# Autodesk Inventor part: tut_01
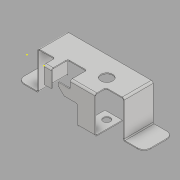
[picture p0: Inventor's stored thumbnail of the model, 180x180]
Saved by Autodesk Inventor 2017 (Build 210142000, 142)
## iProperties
Created: 2015-06
Part Number: tut_01
Material: Generic
Document SubType Name: Sheet Metal
Designer: Sandeep
Density: 1 g/cm^3
Sheet Metal Rule: Default_mm
Appearance: Default
Author: Sandeep
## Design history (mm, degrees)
node "Face1"
  sketch "Sketch1"
    geometry: L1 (0, 12)-(0, 44); L2 (0, 44)-(95, 44); L3 (95, 44)-(95, 12); L4 (95, 12)-(75, 12); L5 (75, 12)-(75, 0); L6 (75, 0)-(48, 0); L7 (48, 0)-(48, 18); L8 (48, 18)-(27, 18); L9 (27, 18)-(27, 0); L10 (27, 0)-(19, 0); L11 (19, 0)-(19, 12); L12 (19, 12)-(0, 12); L13 (0, 0)-(0, 88.508); L14 (0, 0)-(152.255, 0)
    constraints: 28 end point, 11 perpendicular, 4 point on line, 2 vertical, 1 horizontal
    dimensions: "d0" = 26 distance between parallel lines of L2 L8; "d1" = 19 distance between parallel lines of L13 L11; "d2" = 8 distance between parallel lines of L9 L11; "d3" = 32 distance between parallel lines of L12 L2; "d4" = 27 distance between parallel lines of L5 L7; "d5" = 20 distance between parallel lines of L3 L5; "d6" = 95 distance between parallel lines of L1 L3; "d7" = 44 distance between parallel lines of L6 L2
node "Contour Flange1"
sketch "Sketch7"
  geometry: 1 further point
node "Contour Flange3"
  sketch "Sketch10"
    geometry: L1 (0, 0)-(41, 0); L2 (41, 0)-(41, 30)
    constraints: 4 end point, 1 horizontal, 1 perpendicular
    dimensions: "d42" = 41 distance of L1.start L1.end; "d43" = 30 distance of L1.end L2.end
sketch "Sketch11"
  geometry: L1 (-3.447, 20)-(8, 20); L2 (8, 20)-(8, -8.777); L3 (8, -8.777)-(-3.447, -8.777); L4 (-3.447, -8.777)-(-3.447, 20); L5 (-21, 39)-(0, 39) reference; L6 (27, 37)-(27, 0) reference; 1 further point
  constraints: 8 end point, 2 parallel, 1 horizontal, 1 perpendicular
  dimensions: "d44" = 19 distance between parallel lines of L1 L5; "d45" = 19 distance between parallel lines of L6 L2
cut "Cut1" sketch "Sketch11" dims "d46" = 1 (= Thickness), "d47" = 0
node "Face2"
  sketch "Sketch12"
    geometry: L1 (0, -17)-(-13, -17); L2 (-13, -17)-(-13, -7); L3 (-13, -7)-(0, -7); L4 (0, 0)-(0, -17) reference; 1 further point
    constraints: 6 end point, 2 perpendicular, 1 horizontal, 1 point on line
    dimensions: "d54" = 13 distance between parallel lines of L2 L4; "d55" = 10 distance of L1.end L2.end
feature "Corner Round1" dims "d56" = 2
feature "Corner Chamfer1" dims "d57" = 6, "d58" = 6, angle "d59" = 45 deg
node "Flange1"
sketch "Sketch14"
  geometry: 1 further point
hole "Hole1" diameter "d72" = 13; stored, may be unused: countersink angle "d76" = 90 deg, drill point angle "d78" = 0 deg; dims "d70" = 9, "d71" = 22, "d73" = 6, "d74" = 4, "d75" = 2, "d77" = 1 (= Thickness)
hole "Hole2" diameter "d81" = 8; stored, may be unused: countersink angle "d85" = 90 deg, drill point angle "d87" = 0 deg; dims "d79" = 9, "d80" = 22, "d82" = 6, "d83" = 4, "d84" = 2, "d86" = 1 (= Thickness)
feature "Corner Round2" dims "d88" = 7
feature "Corner Round3" dims "d89" = 2
workplane "Work Plane1"
node "Contour Flange4"
  sketch "Sketch15"
    geometry: L1 (0, 0.919)-(0, -40.081); L2 (0, -40.081)-(-22, -40.081); 1 further point
    constraints: 4 end point, 1 perpendicular, 1 vertical
    dimensions: "d90" = 41 distance of L1.start L1.end; "d91" = 22 distance of L1.end L2.end
feature "Corner Round4" dims "d101" = 7
feature "Corner Round5" dims "d102" = 2
body "Solid1"
face "Plate1" dims "Thickness" = 1 (derived)
sketch "Sketch6"
  geometry: L1 (-75, 1)-(20, 1) reference; L2 (20, 1)-(20, -39); L3 (20, -39)-(42, -39); L4 (-75, 1)-(-75, -39); L5 (-75, -39)-(-97, -39); 1 further point
  constraints: 8 end point, 2 perpendicular, 2 vertical
  dimensions: "d9" = 40 distance of L1.end L2.end; "d10" = 22 distance of L2.end L3.end; "d20" = 40 distance of L1.start L4.end
face "Plate2" dims "d11" = 1 (= BendReliefWidth), "d12" = 0.5 (= BendReliefDepth), "d13" = 2 (= MinimumRemnant), "d14" = 1 (= BendRadius), "d15" = 1 (= BendRadius), "d16" = 1, "d17" = 4 (= CornerReliefSize), "d18" = 1 (= GapSize), "d19" = 1 (= JacobiRadiusSize), "SeamGap" = 0.01, "Thickness" = 1 (derived)
bend "Bend1" dims "d11" = 1 (= BendReliefWidth), "d12" = 0.5 (= BendReliefDepth), "d13" = 2 (= MinimumRemnant), "d14" = 1 (= BendRadius), "d15" = 1 (= BendRadius), "d16" = 1, "SeamGap" = 0.01, "Thickness" = 1 (derived)
feature "Corner1" dims "d16" = 1, "d17" = 4 (= CornerReliefSize), "d18" = 1 (= GapSize), "d19" = 1 (= JacobiRadiusSize)
face "Plate4" dims "d33" = 1 (= BendReliefWidth), "d34" = 0.5 (= BendReliefDepth), "d35" = 2 (= MinimumRemnant), "d36" = 1 (= BendRadius), "d37" = 1 (= BendRadius), "d38" = 1, "d39" = 4 (= CornerReliefSize), "d40" = 1 (= GapSize), "d41" = 1 (= JacobiRadiusSize), "SeamGap" = 0.01, "Thickness" = 1 (derived)
bend "Bend3" dims "d33" = 1 (= BendReliefWidth), "d34" = 0.5 (= BendReliefDepth), "d35" = 2 (= MinimumRemnant), "d36" = 1 (= BendRadius), "d37" = 1 (= BendRadius), "d38" = 1, "SeamGap" = 0.01, "Thickness" = 1 (derived)
feature "Corner3" dims "d38" = 1, "d39" = 4 (= CornerReliefSize), "d40" = 1 (= GapSize), "d41" = 1 (= JacobiRadiusSize)
face "Plate5" dims "d49" = 1 (= BendRadius), "d50" = 1 (= BendReliefWidth), "d52" = 2 (= MinimumRemnant), "Thickness" = 1 (derived)
bend "Bend4" dims "d49" = 1 (= BendRadius), "d50" = 1 (= BendReliefWidth), "d51" = 0.5 (= BendReliefDepth), "d52" = 2 (= MinimumRemnant), "d53" = 1 (= BendRadius), "SeamGap" = 0.01, "Thickness" = 1 (derived)
sketch "Sketch13"
  geometry: L1 through (-4, 0) direction (1, 6.84e-48); L2 through (0, 9.5) direction (-4.87e-32, 1); L3 (0, 19)-(-8, 19); L4 (-8, 19)-(-8, 0)
  constraints: 6 end point, 1 horizontal, 1 perpendicular, 1 vertical
face "Plate6" dims "d60" = 1 (= BendReliefWidth), "d61" = 0.5 (= BendReliefDepth), "d62" = 2 (= MinimumRemnant), "d63" = 1 (= BendRadius), "d64" = 19, "d65" = 90 deg, "d66" = 1 (= BendRadius), "d67" = 4 (= CornerReliefSize), "d68" = 1 (= GapSize), "d69" = 1 (= JacobiRadiusSize), "SeamGap" = 0.01, "Thickness" = 1 (derived)
bend "Bend5" dims "d60" = 1 (= BendReliefWidth), "d61" = 0.5 (= BendReliefDepth), "d62" = 2 (= MinimumRemnant), "d63" = 1 (= BendRadius), "d64" = 19, "d65" = 90 deg, "d66" = 1 (= BendRadius), "SeamGap" = 0.01, "Thickness" = 1 (derived)
feature "Corner4" dims "d64" = 19, "d65" = 90 deg, "d67" = 4 (= CornerReliefSize), "d68" = 1 (= GapSize), "d69" = 1 (= JacobiRadiusSize)
face "Plate7" dims "d92" = 1 (= BendReliefWidth), "d93" = 0.5 (= BendReliefDepth), "d94" = 2 (= MinimumRemnant), "d95" = 1 (= BendRadius), "d96" = 1 (= BendRadius), "d97" = 1, "d98" = 4 (= CornerReliefSize), "d99" = 1 (= GapSize), "d100" = 1 (= JacobiRadiusSize), "SeamGap" = 0.01, "Thickness" = 1 (derived)
bend "Bend6" dims "d92" = 1 (= BendReliefWidth), "d93" = 0.5 (= BendReliefDepth), "d94" = 2 (= MinimumRemnant), "d95" = 1 (= BendRadius), "d96" = 1 (= BendRadius), "d97" = 1, "SeamGap" = 0.01, "Thickness" = 1 (derived)
feature "Corner5" dims "d97" = 1, "d98" = 4 (= CornerReliefSize), "d99" = 1 (= GapSize), "d100" = 1 (= JacobiRadiusSize)
other parameters: "BendRadius" = 1 (= Thickness), "BendReliefWidth" = 1 (= Thickness), "BendReliefDepth" = 0.5 (= 0.5 x Thickness), "CornerReliefSize" = 4 (= 4 x Thickness), "MinimumRemnant" = 2 (= 2 x Thickness), "TransitionRadius" = 1 (= BendRadius), "JacobiRadiusSize" = 1 (= BendRadius), "GapSize" = 1 (= Thickness), "d8" = 1 (= BendRadius)
